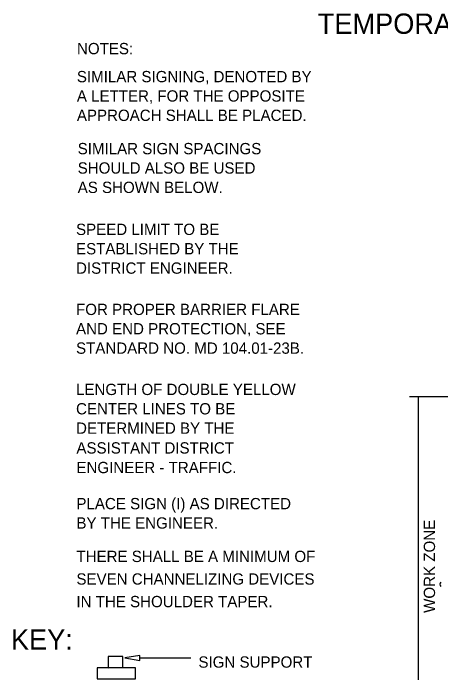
# Model space of a CAD drawing. Extents: x 1531.2 to 1538.6, y 1529.6 to 1539.7.
# Drawn here: x 1531.301 to 1533.576, y 1536.2 to 1539.704 of the extents above; entities that cross this region are included whole.
import ezdxf

# ---------------------------------------------------------------- set-up
doc = ezdxf.new("R2010")
doc.units = 0
for name, color, linetype in [('DETL-DIMS', 7, 'Continuous'), ('DETL-LINE', 7, 'Continuous'), ('DETL-NOTE', 7, 'Continuous'), ('DETL-TITL', 7, 'Continuous'), ('USER-BORD', 7, 'Continuous')]:
    doc.layers.add(name, color=color, linetype=linetype)

# ---------------------------------------------------------------- blocks, each defined once
blk = doc.blocks.new('SIGN13')
at = {"layer": 'USER-BORD'}
for points in [[(-0.0134, 0.0182), (0.011, 0.0189), (0.011, 0.0371), (-0.0134, 0.0371)], [(-0.0314, 0.0182), (-0.0314, 0), (0.032, 0), (0.032, 0.0182)]]:
    blk.add_lwpolyline(points, close=True, dxfattribs=at)

msp = doc.modelspace()

# ---------------------------------------------------------------- linework, layer by layer
at = {"layer": 'DETL-DIMS'}
for p, q in [((1533.4083, 1537.6671), (1534.2295, 1537.6671)), ((1533.4563, 1535.8707), (1533.4563, 1537.6671)), ((1531.9752, 1536.2786), (1532.2457, 1536.2786))]:
    msp.add_line(p, q, dxfattribs=at)
msp.add_lwpolyline([(1531.9752, 1536.2652), (1531.9752, 1536.292), (1531.8952, 1536.2786)], close=True, dxfattribs=at)
at = {"layer": 'DETL-LINE'}
msp.add_arc((1533.5869, 1536.6702), 0.016, 135, 225, dxfattribs=at)

# ---------------------------------------------------------------- block references
at = {"layer": 'DETL-LINE', "xscale": 3.2, "yscale": 3.2000000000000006}
msp.add_blockref('SIGN13', (1531.8493, 1536.167), dxfattribs=at)

# ---------------------------------------------------------------- texts
at = {"layer": 'DETL-NOTE'}
for s, p in [('NOTES:', (1531.6408, 1539.4855)), ('SIMILAR SIGNING, DENOTED BY', (1531.6402, 1539.3367)), ('A LETTER, FOR THE OPPOSITE', (1531.6402, 1539.2339)), ('APPROACH SHALL BE PLACED.', (1531.6402, 1539.1311)), ('SIMILAR SIGN SPACINGS', (1531.6445, 1538.9542)), ('SHOULD ALSO BE USED ', (1531.6445, 1538.8513)), ('AS SHOWN BELOW.', (1531.6445, 1538.7484)), ('SPEED LIMIT TO BE', (1531.6357, 1538.5253)), ('ESTABLISHED BY THE', (1531.6357, 1538.4224)), ('DISTRICT ENGINEER.', (1531.6357, 1538.3195)), ('FOR PROPER BARRIER FLARE', (1531.6357, 1538.1002)), ('AND END PROTECTION, SEE', (1531.6357, 1537.9973)), ('STANDARD NO. MD 104.01-23B.', (1531.6357, 1537.8944)), ('LENGTH OF DOUBLE YELLOW', (1531.6357, 1537.6751)), ('CENTER LINES TO BE', (1531.6357, 1537.5722)), ('DETERMINED BY THE', (1531.6357, 1537.4693)), ('ASSISTANT DISTRICT', (1531.6377, 1537.3642)), ('ENGINEER - TRAFFIC.', (1531.6377, 1537.2602)), ('PLACE SIGN (I) AS DIRECTED', (1531.6377, 1537.0683)), ('BY THE ENGINEER.', (1531.6377, 1536.9655)), ('THERE SHALL BE A MINIMUM OF ', (1531.6377, 1536.788)), ('SEVEN CHANNELIZING DEVICES ', (1531.6377, 1536.668)), ('IN THE SHOULDER TAPER.', (1531.6377, 1536.548)), ('SIGN SUPPORT', (1532.2866, 1536.2268))]:
    msp.add_text(s, height=0.06, dxfattribs=at).set_placement(p)
msp.add_text('WORK ZONE', height=0.06, rotation=90, dxfattribs=at).set_placement((1533.545, 1536.5179))
at = {"layer": 'DETL-TITL'}
for s, p in [('TEMPORARY TRAFFIC CONTROL TYPICAL APPLICATION', (1532.9213, 1539.5939)), ('KEY:', (1531.2895, 1536.3224))]:
    msp.add_text(s, height=0.108, dxfattribs=at).set_placement(p)

doc.saveas('drawing.dxf')
